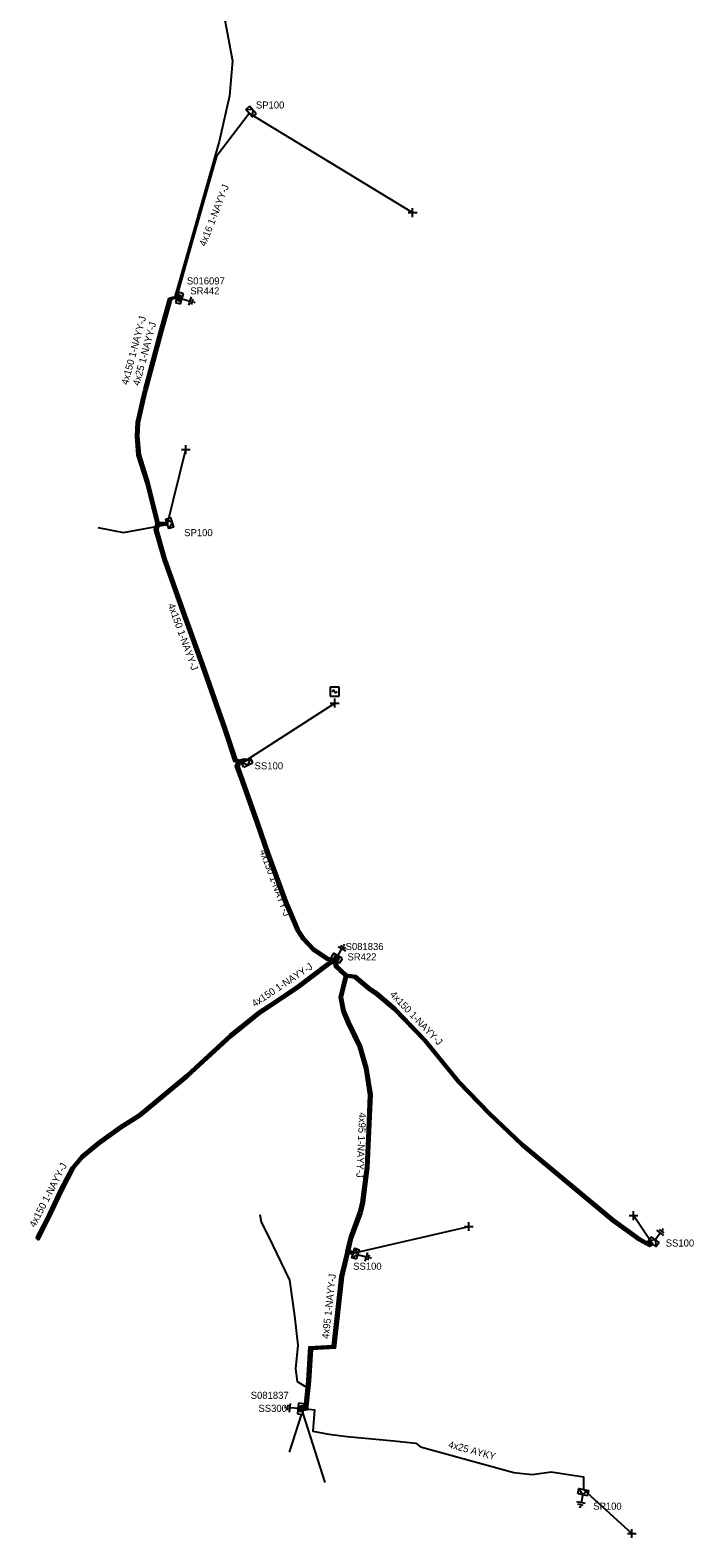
# Model space of a CAD drawing. Extents: x -717562 to -713845, y -1151196 to -1143903.
# Drawn here: x -716917 to -716823.4, y -1145411.5 to -1145198.5 of the extents above; entities that cross this region are included whole.
import ezdxf

# ---------------------------------------------------------------- set-up
doc = ezdxf.new("R2010")
doc.units = 0
for name, color, linetype in [('Vrstva 1', 7, 'Continuous'), ('Vrstva 14', 7, 'Continuous'), ('Vrstva 15', 7, 'Continuous'), ('Vrstva 20', 7, 'Continuous'), ('Vrstva 28', 7, 'Continuous'), ('Vrstva 29', 7, 'Continuous'), ('Vrstva 30', 7, 'Continuous'), ('Vrstva 31', 7, 'Continuous'), ('Vrstva 33', 7, 'Continuous'), ('Vrstva 34', 7, 'Continuous'), ('Vrstva 5', 7, 'Continuous'), ('Vrstva 52', 7, 'Continuous'), ('Vrstva 54', 7, 'Continuous'), ('Vrstva 59', 7, 'Continuous'), ('Vrstva 6', 7, 'Continuous'), ('Vrstva 8', 7, 'Continuous'), ('Vrstva 9', 7, 'Continuous')]:
    doc.layers.add(name, color=color, linetype=linetype)

# ---------------------------------------------------------------- blocks, each defined once
blk = doc.blocks.new('NN800')
at = {"layer": 'Vrstva 1'}
for points in [[(-0.44, 0.44), (0.44, -0.44)], [(-0.44, -0.44), (0.44, 0.44)]]:
    blk.add_lwpolyline(points, dxfattribs=at)
blk = doc.blocks.new('NN620')
at = {"layer": 'Vrstva 8'}
for points in [[(0.75, 0), (-0.75, 0)], [(-0.75, 0), (-0.75, -0.75)], [(0.75, -0.75), (0.75, 0)], [(-0.75, -0.75), (0.75, -0.75)], [(0.37, -0.18), (-0.38, -0.18)], [(-0.38, -0.18), (-0.38, -0.56)], [(-0.38, -0.56), (0.37, -0.56)], [(0.32, -0.23), (-0.33, -0.23)], [(-0.33, -0.23), (-0.33, -0.51)], [(-0.33, -0.51), (0.32, -0.51)], [(0.27, -0.27), (-0.28, -0.27)], [(-0.28, -0.27), (-0.28, -0.46)], [(-0.28, -0.46), (0.27, -0.46)], [(0.23, -0.32), (-0.23, -0.32)], [(-0.23, -0.32), (-0.23, -0.42)], [(-0.23, -0.42), (0.23, -0.42)], [(-0.19, -0.37), (0.19, -0.37)], [(0.23, -0.42), (0.23, -0.32)], [(0.27, -0.46), (0.27, -0.27)], [(0.32, -0.51), (0.32, -0.23)], [(0.37, -0.56), (0.37, -0.18)]]:
    blk.add_lwpolyline(points, dxfattribs=at)
blk = doc.blocks.new('NN630')
at = {"layer": 'Vrstva 9'}
for points in [[(0, -0.7), (-0.7, 0)], [(-0.7, -0.7), (-0.7, 0), (0.7, 0), (0.7, -0.7)], [(-0.7, -0.7), (0.7, -0.7)], [(0, -0.7), (0.7, 0)]]:
    blk.add_lwpolyline(points, dxfattribs=at)
blk = doc.blocks.new('NN810')
at = {"layer": 'Vrstva 14'}
for points in [[(0.63, -1.89), (-0.62, -1.89)], [(0, -0.64), (0, -1.89)], [(0.39, -2.2), (-0.4, -2.2)], [(0, -2.52), (-0.12, -2.52)], [(0.14, -2.52), (0, -2.52)]]:
    blk.add_lwpolyline(points, dxfattribs=at)
blk = doc.blocks.new('NN740')
at = {"layer": 'Vrstva 1'}
for points in [[(0.62, 0.62), (-0.63, 0.62)], [(-0.63, 0.62), (-0.63, -0.63)], [(0, 0), (0, 0.01), (0, 0.03), (-0.01, 0.05), (-0.01, 0.06), (-0.02, 0.08), (-0.03, 0.09), (-0.04, 0.1), (-0.05, 0.11), (-0.06, 0.12), (-0.08, 0.13), (-0.09, 0.14), (-0.11, 0.14), (-0.12, 0.15), (-0.14, 0.15), (-0.15, 0.15), (-0.17, 0.15), (-0.18, 0.15), (-0.2, 0.15), (-0.21, 0.14), (-0.23, 0.13), (-0.24, 0.12), (-0.26, 0.11), (-0.27, 0.1), (-0.28, 0.09), (-0.29, 0.08), (-0.29, 0.06), (-0.3, 0.05), (-0.3, 0.03), (-0.31, 0.02), (-0.31, 0), (-0.31, 0)], [(0.62, -0.63), (0.62, 0.62)], [(-0.63, -0.63), (0.62, -0.63)], [(0, 0), (0, -0.02), (0, -0.03), (0.01, -0.05), (0.01, -0.06), (0.02, -0.08), (0.03, -0.09), (0.04, -0.1), (0.05, -0.11), (0.06, -0.12), (0.07, -0.13), (0.09, -0.14), (0.1, -0.15), (0.12, -0.15), (0.13, -0.15), (0.15, -0.15), (0.16, -0.15), (0.18, -0.15), (0.19, -0.15), (0.21, -0.14), (0.22, -0.14), (0.24, -0.13), (0.25, -0.12), (0.26, -0.11), (0.27, -0.09), (0.28, -0.08), (0.29, -0.07), (0.29, -0.05), (0.3, -0.04), (0.3, -0.02), (0.3, -0.01), (0.3, -0.01)]]:
    blk.add_lwpolyline(points, dxfattribs=at)

msp = doc.modelspace()

# ---------------------------------------------------------------- linework, layer by layer
at = {"layer": 'Vrstva 20'}
for points in [[(-716899.22, -1145268.34), (-716900.67, -1145262.51), (-716901.91, -1145258.57), (-716902.12, -1145255.86), (-716902.04, -1145253.91), (-716901.18, -1145250.18), (-716900.95, -1145249.21), (-716898.78, -1145241.13), (-716897.47, -1145236.42), (-716897.09, -1145236.52), (-716898.4, -1145241.23), (-716900.57, -1145249.31), (-716900.8, -1145250.28), (-716901.64, -1145253.97), (-716901.72, -1145255.86), (-716901.51, -1145258.49), (-716900.29, -1145262.41), (-716898.84, -1145268.24)], [(-716897.65, -1145268.46), (-716899.03, -1145268.49), (-716899.03, -1145268.09), (-716897.65, -1145268.06)], [(-716890.62, -1145294.74), (-716892.91, -1145288.26), (-716895.39, -1145281.39), (-716898.28, -1145273.31), (-716899.49, -1145269.05), (-716899.22, -1145268.23), (-716898.84, -1145268.35), (-716899.07, -1145269.05), (-716897.9, -1145273.19), (-716895.01, -1145281.25), (-716892.53, -1145288.12), (-716890.24, -1145294.6)], [(-716887.57, -1145302.02), (-716888.22, -1145301.86), (-716889.74, -1145297.26), (-716890.62, -1145294.74), (-716890.24, -1145294.6), (-716889.36, -1145297.14), (-716887.9, -1145301.52), (-716887.47, -1145301.64)], [(-716874, -1145330.14), (-716875.08, -1145329.94), (-716877.17, -1145328.55), (-716878.57, -1145327.03), (-716879.45, -1145325.74), (-716881.18, -1145321.66), (-716883.68, -1145314.89), (-716885.13, -1145310.66), (-716887.26, -1145304.68), (-716888.04, -1145302.51), (-716887.7, -1145301.75), (-716887.34, -1145301.91), (-716887.6, -1145302.53), (-716886.88, -1145304.54), (-716884.75, -1145310.52), (-716883.3, -1145314.75), (-716880.8, -1145321.52), (-716879.09, -1145325.54), (-716878.25, -1145326.79), (-716876.91, -1145328.25), (-716874.92, -1145329.56), (-716873.92, -1145329.74)], [(-716886.63, -1145301.91), (-716886.85, -1145301.86), (-716887.47, -1145302.02), (-716887.57, -1145301.64), (-716886.85, -1145301.44), (-716886.53, -1145301.53)], [(-716882.84, -1145335.88), (-716879.49, -1145333.65), (-716875.06, -1145330.3), (-716874.05, -1145329.76), (-716873.87, -1145330.12), (-716874.84, -1145330.64), (-716879.25, -1145333.97), (-716882.62, -1145336.22)], [(-716872.54, -1145332.23), (-716873.37, -1145331.5), (-716874.04, -1145330.89), (-716874.16, -1145329.97), (-716873.76, -1145329.91), (-716873.66, -1145330.69), (-716873.11, -1145331.2), (-716872.28, -1145331.93)], [(-716873.01, -1145337.15), (-716873.39, -1145335.12), (-716872.6, -1145332.03), (-716872.22, -1145332.13), (-716872.99, -1145335.14), (-716872.61, -1145337.07)], [(-716872.38, -1145331.88), (-716871.07, -1145332.07), (-716868.96, -1145333.87), (-716868.12, -1145334.4), (-716865.42, -1145336.69), (-716861.18, -1145341.12), (-716856.39, -1145346.99), (-716852.08, -1145351.46), (-716847.44, -1145355.85), (-716839.7, -1145362.31), (-716834.66, -1145366.5), (-716830.86, -1145369.22), (-716829.6, -1145369.92), (-716829.34, -1145369.79), (-716829.16, -1145370.15), (-716829.62, -1145370.38), (-716831.08, -1145369.56), (-716834.9, -1145366.82), (-716839.96, -1145362.61), (-716847.7, -1145356.15), (-716852.36, -1145351.74), (-716856.69, -1145347.25), (-716861.48, -1145341.38), (-716865.7, -1145336.99), (-716868.36, -1145334.72), (-716869.2, -1145334.19), (-716871.25, -1145332.45), (-716872.44, -1145332.28)], [(-716916.18, -1145369.14), (-716914.79, -1145366.45), (-716912.79, -1145362.22), (-716911.19, -1145359.19), (-716909.83, -1145357.56), (-716907.41, -1145355.56), (-716904.38, -1145353.38), (-716901.7, -1145351.67), (-716895.02, -1145346.13), (-716888.85, -1145340.44), (-716884.81, -1145337.16), (-716882.84, -1145335.88), (-716882.62, -1145336.22), (-716884.57, -1145337.48), (-716888.59, -1145340.74), (-716894.76, -1145346.43), (-716901.46, -1145351.99), (-716904.16, -1145353.72), (-716907.17, -1145355.88), (-716909.55, -1145357.84), (-716910.85, -1145359.41), (-716912.43, -1145362.4), (-716914.43, -1145366.63), (-716915.86, -1145369.41)], [(-716872.63, -1145337.03), (-716871.98, -1145338.6), (-716870.3, -1145342.01), (-716869.4, -1145345.13), (-716868.82, -1145348.91), (-716869.03, -1145354.06), (-716869.26, -1145359.19), (-716869.91, -1145364.19), (-716870.24, -1145365.61), (-716871.6, -1145369.22), (-716872.01, -1145371.09), (-716872.41, -1145371.01), (-716871.98, -1145369.1), (-716870.62, -1145365.49), (-716870.31, -1145364.11), (-716869.66, -1145359.15), (-716869.43, -1145354.04), (-716869.22, -1145348.93), (-716869.8, -1145345.21), (-716870.68, -1145342.15), (-716872.34, -1145338.76), (-716872.99, -1145337.19)], [(-716872.02, -1145371.1), (-716872.87, -1145374.66), (-716873.98, -1145384.72), (-716877.25, -1145384.94), (-716877.52, -1145389.39), (-716877.92, -1145389.37), (-716877.63, -1145384.56), (-716874.34, -1145384.34), (-716873.27, -1145374.6), (-716872.4, -1145371)], [(-716872.15, -1145370.86), (-716871.36, -1145371.11), (-716871.48, -1145371.49), (-716872.27, -1145371.24)], [(-716877.52, -1145389.4), (-716877.94, -1145393.45), (-716878.43, -1145393.55), (-716878.51, -1145393.15), (-716878.3, -1145393.11), (-716877.92, -1145389.36)]]:
    msp.add_lwpolyline(points, close=True, dxfattribs=at)
at = {"layer": 'Vrstva 5'}
for points in [[(-716909.51, -1145133.21), (-716909.25, -1145133.1), (-716904.98, -1145132.04), (-716900.94, -1145152.56), (-716897.11, -1145168.92), (-716894.6, -1145171.74), (-716894.8, -1145173.99), (-716890.82, -1145190.27), (-716888.46, -1145202.85), (-716888.9, -1145207.8), (-716890.34, -1145214.23), (-716896.35, -1145235.19), (-716896.58, -1145235.97), (-716896.25, -1145236.05)], [(-716896.31, -1145236.25), (-716896.5, -1145236.19), (-716897.36, -1145236.39), (-716898.69, -1145241.15), (-716900.86, -1145249.24), (-716901.09, -1145250.21), (-716901.94, -1145253.93), (-716902.02, -1145255.86), (-716901.81, -1145258.55), (-716900.58, -1145262.49), (-716899.09, -1145268.47), (-716899.28, -1145269.05), (-716898.09, -1145273.25), (-716895.2, -1145281.32), (-716892.72, -1145288.19), (-716890.43, -1145294.67), (-716889.55, -1145297.2), (-716888.06, -1145301.69), (-716887.72, -1145301.78), (-716886.85, -1145301.55), (-716886.58, -1145301.72), (-716886.85, -1145301.75), (-716887.57, -1145301.95), (-716887.82, -1145302.52), (-716887.07, -1145304.61), (-716884.94, -1145310.59), (-716883.49, -1145314.82), (-716880.99, -1145321.59), (-716879.27, -1145325.64), (-716878.41, -1145326.91), (-716877.04, -1145328.4), (-716875, -1145329.75), (-716874.39, -1145329.86), (-716874.18, -1145329.81)], [(-716896.37, -1145236.47), (-716896.59, -1145236.42), (-716897.2, -1145236.55), (-716898.49, -1145241.21), (-716900.66, -1145249.28), (-716900.89, -1145250.25), (-716901.74, -1145253.95), (-716901.82, -1145255.86), (-716901.61, -1145258.51), (-716900.38, -1145262.43), (-716898.93, -1145268.29), (-716897.65, -1145268.26)], [(-716873.96, -1145329.94), (-716874.95, -1145330.47), (-716879.37, -1145333.81), (-716882.73, -1145336.05), (-716884.69, -1145337.32), (-716888.72, -1145340.59), (-716894.89, -1145346.28), (-716901.58, -1145351.83), (-716904.27, -1145353.55), (-716907.29, -1145355.72), (-716909.69, -1145357.7), (-716911.02, -1145359.3), (-716912.61, -1145362.31), (-716914.61, -1145366.54), (-716916.02, -1145369.28)], [(-716873.78, -1145330.05), (-716874.01, -1145330.35), (-716873.94, -1145330.84), (-716873.31, -1145331.42), (-716872.44, -1145332.19), (-716873.19, -1145335.13), (-716872.81, -1145337.11), (-716872.16, -1145338.68), (-716870.49, -1145342.08), (-716869.6, -1145345.17), (-716869.02, -1145348.92), (-716869.23, -1145354.05), (-716869.46, -1145359.17), (-716870.11, -1145364.15), (-716870.43, -1145365.55), (-716871.79, -1145369.16), (-716872.19, -1145370.95), (-716871.6, -1145371.14), (-716871.42, -1145371.3), (-716871.64, -1145371.34), (-716872.23, -1145371.15), (-716873.07, -1145374.63), (-716874.16, -1145384.53), (-716877.44, -1145384.75), (-716877.72, -1145389.38), (-716878.11, -1145393.15), (-716878.46, -1145393.14)], [(-716873.61, -1145330.11), (-716873.8, -1145330.37), (-716873.76, -1145330.74), (-716873.17, -1145331.28), (-716872.23, -1145332.11), (-716871.16, -1145332.26), (-716869.08, -1145334.03), (-716868.24, -1145334.56), (-716865.56, -1145336.84), (-716861.33, -1145341.25), (-716856.54, -1145347.12), (-716852.22, -1145351.6), (-716847.57, -1145356), (-716839.83, -1145362.46), (-716834.78, -1145366.66), (-716830.97, -1145369.39), (-716829.61, -1145370.15), (-716829.25, -1145369.97)], [(-716878.47, -1145393.35), (-716878.06, -1145393.29), (-716876.89, -1145393.47), (-716877.14, -1145396.47), (-716874.88, -1145396.87), (-716872.27, -1145397.2), (-716865.7, -1145397.84), (-716862.61, -1145398.18), (-716861.92, -1145398.68), (-716848.77, -1145402.3), (-716846.16, -1145402.57), (-716843.5, -1145402.21), (-716838.91, -1145402.91), (-716838.91, -1145404.72)]]:
    msp.add_lwpolyline(points, dxfattribs=at)
at = {"layer": 'Vrstva 52'}
msp.add_lwpolyline([(-716896.19, -1145235.84), (-716896.24, -1145235.67), (-716896.07, -1145235.23), (-716894.1, -1145228.36), (-716890.66, -1145216.17), (-716886.14, -1145210.24)], dxfattribs=at)
at = {"layer": 'Vrstva 59'}
for points in [[(-716886.14, -1145210.24), (-716863.05, -1145224.28)], [(-716897.65, -1145268.26), (-716895.06, -1145257.75)], [(-716886.58, -1145301.72), (-716874.05, -1145293.58)], [(-716829.25, -1145369.97), (-716831.86, -1145366.01)], [(-716871.42, -1145371.3), (-716855.11, -1145367.54)], [(-716878.74, -1145394), (-716880.48, -1145399.44)], [(-716878.56, -1145393.99), (-716875.42, -1145403.73)], [(-716838.91, -1145404.72), (-716832.1, -1145410.92)]]:
    msp.add_lwpolyline(points, dxfattribs=at)
at = {"layer": 'Vrstva 9'}
for points in [[(-716907.5, -1145268.79), (-716903.86, -1145269.49), (-716897.68, -1145268.33)], [(-716884.61, -1145365.85), (-716884.43, -1145366.91), (-716882.84, -1145370.15), (-716880.42, -1145375.14), (-716879.7, -1145380.17), (-716879.27, -1145384.33), (-716879.56, -1145387.66), (-716879.33, -1145389.43), (-716878.04, -1145390.24), (-716877.78, -1145390.94), (-716877.92, -1145392.12), (-716878.03, -1145393.08), (-716878.62, -1145393.35)]]:
    msp.add_lwpolyline(points, dxfattribs=at)

# ---------------------------------------------------------------- block references
at = {"layer": 'Vrstva 15'}
for p, rotation in [((-716896.31, -1145236.25), 73.55141416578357), ((-716873.96, -1145329.94), 150.25510770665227), ((-716829.25, -1145369.97), 143.1300909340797), ((-716871.42, -1145371.3), 73.39299133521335), ((-716878.47, -1145393.35), -95.71057443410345), ((-716838.91, -1145404.72), -11.325053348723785)]:
    msp.add_blockref('NN810', p, dxfattribs=dict(at, rotation=rotation))
at = {"layer": 'Vrstva 28'}
for p, rotation in [((-716896.31, -1145236.25), 73.55141416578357), ((-716873.96, -1145329.94), 150.25510770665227), ((-716878.47, -1145393.35), -95.78646299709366)]:
    msp.add_blockref('NN620', p, dxfattribs=dict(at, rotation=rotation))
at = {"layer": 'Vrstva 31'}
for p, rotation in [((-716886.14, -1145210.24), 131.60193055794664), ((-716897.65, -1145268.26), 107.75109445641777), ((-716886.58, -1145301.72), 26.952183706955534), ((-716829.25, -1145369.97), 143.1300909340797), ((-716871.42, -1145371.3), 73.39299133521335), ((-716838.91, -1145404.72), -11.990301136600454)]:
    msp.add_blockref('NN630', p, dxfattribs=dict(at, rotation=rotation))
at = {"layer": 'Vrstva 34', "rotation": 45}
for p in [(-716863.05, -1145224.28), (-716895.06, -1145257.75), (-716874.05, -1145293.58), (-716831.86, -1145366.01), (-716855.11, -1145367.54), (-716832.1, -1145410.92)]:
    msp.add_blockref('NN800', p, dxfattribs=at)
at = {"layer": 'Vrstva 34'}
msp.add_blockref('NN740', (-716874.06, -1145291.96), dxfattribs=at)

# ---------------------------------------------------------------- texts
at = {"layer": 'Vrstva 29'}
for s, p in [('S016097', (-716894.91, -1145234.43)), ('S081836', (-716872.51, -1145328.48)), ('S081837', (-716885.9, -1145391.9))]:
    msp.add_text(s, height=1, dxfattribs=at).set_placement(p)
at = {"layer": 'Vrstva 30'}
for s, p in [('SR442', (-716894.42, -1145235.84)), ('SR422', (-716872.24, -1145329.95)), ('SS300', (-716884.81, -1145393.74))]:
    msp.add_text(s, height=1, dxfattribs=at).set_placement(p)
at = {"layer": 'Vrstva 33'}
for s, p in [('SP100', (-716885.17, -1145209.57)), ('SP100', (-716895.29, -1145270)), ('SS100', (-716885.35, -1145302.95)), ('SS100', (-716827.32, -1145370.38)), ('SS100', (-716871.44, -1145373.66)), ('SP100', (-716837.56, -1145407.56))]:
    msp.add_text(s, height=1, dxfattribs=at).set_placement(p)
at = {"layer": 'Vrstva 54'}
msp.add_text('4x16 1-NAYY-J', height=1, rotation=68.712, dxfattribs=at).set_placement((-716892.29, -1145229.13))
at = {"layer": 'Vrstva 6'}
for s, rotation, p in [('4x150 1-NAYY-J', 74.967, (-716903.24, -1145248.69)), ('4x25 1-NAYY-J', 74.967, (-716901.62, -1145248.8)), ('4x150 1-NAYY-J', 289.849, (-716897.61, -1145279.7)), ('4x150 1-NAYY-J', 290.268, (-716884.66, -1145314.48)), ('4x150 1-NAYY-J', 33.69, (-716885.34, -1145336.58)), ('4x150 1-NAYY-J', 313.807, (-716866.33, -1145334.84)), ('4x95 1-NAYY-J', 267.428, (-716870.59, -1145351.43)), ('4x150 1-NAYY-J', 62.74, (-716916.35, -1145367.76)), ('4x95 1-NAYY-J', 83.717, (-716874.88, -1145383.46)), ('4x25 AYKY', 344.989, (-716858.09, -1145398.78))]:
    msp.add_text(s, height=1, rotation=rotation, dxfattribs=at).set_placement(p)

doc.saveas('drawing.dxf')
